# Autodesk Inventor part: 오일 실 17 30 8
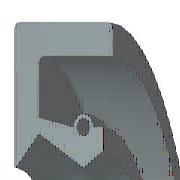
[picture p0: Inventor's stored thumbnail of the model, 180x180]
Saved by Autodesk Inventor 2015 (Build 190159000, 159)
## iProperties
IsCustomPart: 1
Created: 2012-02
Part Number: 오일 실 17 30 8
Material: 고무
Description: 오일-실
Document SubType Name: Modeling
Standard: KS B 2804
Designer: mduedu
Standards Organization: KS
Language: ko-KR
Size Designation: D - 17 30 8
Categories: <MemberInstance><Categories><Category DisplayName="샤프트 부품" InternalName="7f7aeb1f-a693-4053-b835-cee3144e0d98" Mnemonic="SHFT"><Category DisplayName="실링" Intern
Density: 0.93 g/cm^3
Appearance: 고무 - 검은색 - 버전 1.1
Author: mduedu
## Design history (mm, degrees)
revolve "본체" stored, may be unused: angle "d17" = 90 deg
revolve "스프링1" stored, may be unused: angle "d18" = 90 deg
body "Solid1"
sketch "스케치1"
  geometry: L1 (0, 15)-(8, 15); L2 (8, 13.25)-(1.75, 13.25); L3 (1.75, 10.25)-(4.9, 8.5); L4 (4.9, 8.5)-(0, 8.5); L5 (0, 0)-(9.586, 0) reference; L6 (4.9, 8.5)-(6.3, 9.375); L7 (0, 18)-(0, -3) reference; L8 (-1.941, 0)-(11.507, 0) reference; L9 (4.2, 10.6)-(1.75, 11.21); L10 (1.75, 11.21)-(1.75, 13.25); L11 (0, 15)-(0, 8.588); L12 (4.9, 8.5)-(0, 8.5); L13 (1.75, 10.25)-(0.152, 8.528); L14 (8, 15)-(8, 13.25); L15 (5.6, 10.6)-(6.3, 10.6); L16 (6.3, 10.6)-(6.3, 9.375); C1 r 0.455 at (4.9, 10.6); A1 r 0.7 centre (4.9, 10.6) between (5.6, 10.6) and (4.2, 10.6); A2 r 0.088 centre (0.088, 8.588) between (0, 8.588) and (0.152, 8.528); 1 further point
  constraints: 28 end point, 5 horizontal alignment, 5 point on line, 4 point on circle, 4 vertical alignment, 3 centre point, 3 tangent, 2 collinear, 2 horizontal, 2 perpendicular, 1 coincident, 1 parallel
  dimensions: "d0" = 30 diameter of L1 L5 (= SD2); "d1" = 1.75 distance of L1.end L2.start (= SD); "d2" = 0.91 diameter of C1 (= SPDI); "d3" = 1.4 diameter of A1 (= SPDA); "d4" = 17 diameter of L3.end L5 (= NND); "d5" = 20.5 diameter of L3.start L5 (= TKDM); "d7" = 22.42 diameter of L9.end L5 (= TKDM + 0.24 x SWDT); "d8" = 1.75 distance between parallel lines of L11 L10 (= SD); "d9" = 4.9 distance from line of L11 C1.centre (= SPDST); "d10" = 21.2 diameter of C1.centre L5 (= HLDM); "d11" = 0.0875 radius of A2 (= 0.25 x LAB); "d12" = 6.3 distance between parallel lines of L11 L16 (= SDI); "d13" = 18.75 diameter of L6.end L5 (= ABDM); "d14" = 8 distance from line of L11 L1.end (= SWDT)
fillet "모깎기1" dims "d6" = 0.3 (= RR)
other parameters: "SD2" = 30 [user parameter; used in 1 equation term], "SWDT" = 8 [user parameter; used in 2 equation terms], "RR" = 0.3 [user parameter; used in 1 equation term], "SD" = 1.75 [user parameter; used in 2 equation terms], "NND" = 17 [user parameter; used in 1 equation term], "SPDA" = 1.4 [user parameter; used in 1 equation term], "SPDI" = 0.91 [user parameter; used in 1 equation term], "TKDM" = 20.5 [user parameter; used in 2 equation terms], "HLDM" = 21.2 [user parameter; used in 1 equation term], "ABDM" = 18.75 [user parameter; used in 1 equation term], "SDI" = 6.3 [user parameter; used in 1 equation term], "SPDST" = 4.9 [user parameter; used in 1 equation term], "LAB" = 0.35 [user parameter; used in 1 equation term], "d15" = 0, "d16" = 0, "d19" = 0
